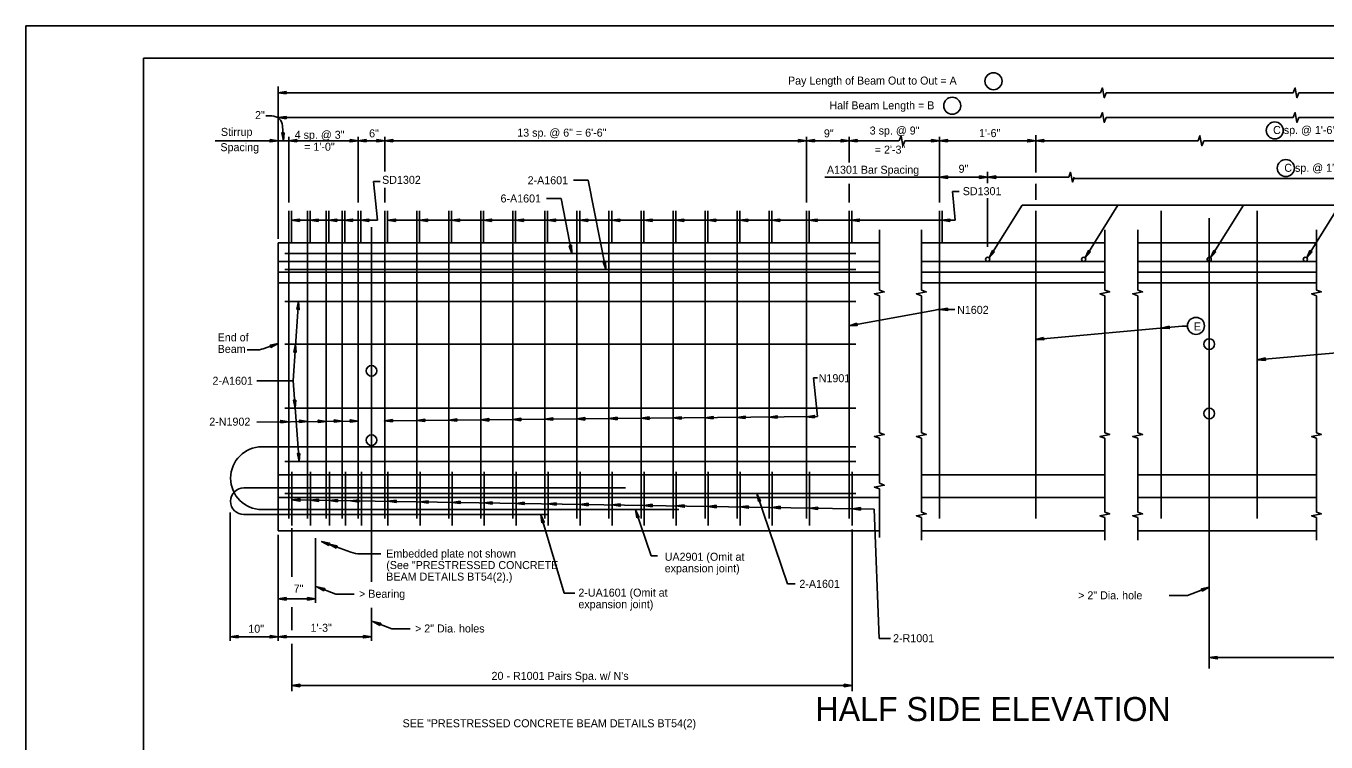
# Model space of a CAD drawing. Extents: x -125.5 to -89.3, y 42.4 to 64.4.
# Drawn here: x -125.53 to -105.23, y 53.27 to 64.45 of the extents above; entities that cross this region are included whole.
import ezdxf

# ---------------------------------------------------------------- set-up
doc = ezdxf.new("R2010")
doc.units = 0
for name, color, linetype in [('BR_AUTO DIMENSION', 7, 'Continuous'), ('BR_BORDER LINES', 7, 'Continuous'), ('BR_CENTER LINES', 7, 'Continuous'), ('BR_PRESTRESSED BEAM', 7, 'Continuous'), ('BR_REBAR', 7, 'Continuous'), ('BR_TEXT', 7, 'Continuous'), ('Level 31', 7, 'Continuous')]:
    doc.layers.add(name, color=color, linetype=linetype)

msp = doc.modelspace()

# ---------------------------------------------------------------- linework, layer by layer
at = {"layer": 'BR_AUTO DIMENSION'}
for p, q in [((-121.596, 61.128), (-121.596, 63.505)), ((-121.596, 63.406), (-108.753, 63.406)), ((-108.666, 63.406), (-105.743, 63.406)), ((-105.657, 63.406), (-98.103, 63.406)), ((-121.693, 63.044), (-121.789, 63.044)), ((-121.596, 63.019), (-108.753, 63.019)), ((-108.666, 63.019), (-105.743, 63.019)), ((-105.657, 63.019), (-98.103, 63.019)), ((-121.512, 62.657), (-121.526, 62.888)), ((-109.766, 62.162), (-109.766, 62.743)), ((-122.577, 62.657), (-114.512, 62.657)), ((-121.429, 61.693), (-121.429, 62.719)), ((-120.346, 61.693), (-120.346, 62.719)), ((-119.929, 62.177), (-119.929, 62.719)), ((-114.512, 62.657), (-113.679, 62.657)), ((-113.679, 62.657), (-111.903, 62.657)), ((-113.346, 61.693), (-113.346, 62.719)), ((-112.679, 62.317), (-112.679, 62.719)), ((-111.81, 62.657), (-107.23, 62.657)), ((-111.266, 61.693), (-111.266, 62.719)), ((-107.143, 62.657), (-98.857, 62.657)), ((-110.516, 61.996), (-110.516, 62.174)), ((-120.108, 62.019), (-120.004, 62.019)), ((-120.045, 61.416), (-120.108, 62.019)), ((-119.929, 61.693), (-119.929, 61.92)), ((-116.754, 62.042), (-116.985, 62.042)), ((-116.478, 60.648), (-116.754, 62.042)), ((-113.061, 62.088), (-109.251, 62.088)), ((-112.679, 61.693), (-112.679, 61.983)), ((-109.766, 61.735), (-109.766, 61.984)), ((-109.164, 62.067), (-98.857, 62.067)), ((-117.177, 61.757), (-117.407, 61.757)), ((-117.007, 60.898), (-117.177, 61.757)), ((-111.064, 61.866), (-110.96, 61.866)), ((-111.025, 61.416), (-111.064, 61.866)), ((-110.516, 60.999), (-110.516, 61.762)), ((-110.491, 60.827), (-109.978, 61.65)), ((-109.978, 61.65), (-103.514, 61.65)), ((-108.995, 60.827), (-108.481, 61.65)), ((-107.035, 60.827), (-106.522, 61.65)), ((-105.534, 60.827), (-105.021, 61.65)), ((-120.045, 61.416), (-121.387, 61.416)), ((-111.025, 61.416), (-119.887, 61.416)), ((-121.288, 59.992), (-121.277, 60.148)), ((-121.362, 58.906), (-121.288, 59.992)), ((-112.679, 59.769), (-111.337, 60.014)), ((-111.248, 60.022), (-111.03, 60.022)), ((-106.306, 59.235), (-98.317, 59.954)), ((-109.766, 59.555), (-107.477, 59.761)), ((-107.477, 59.761), (-107.395, 59.761)), ((-121.831, 59.408), (-121.596, 59.49)), ((-122.078, 59.39), (-121.94, 59.39)), ((-121.927, 58.906), (-121.362, 58.906)), ((-121.362, 58.906), (-121.267, 57.648)), ((-113.175, 58.35), (-113.238, 58.953)), ((-113.238, 58.953), (-113.174, 58.953)), ((-120.346, 58.28), (-121.926, 58.265)), ((-113.175, 58.35), (-119.935, 58.284)), ((-121.38, 57.05), (-112.286, 56.905)), ((-114.12, 57.148), (-113.642, 55.738)), ((-122.346, 56.852), (-122.346, 54.85)), ((-116.016, 56.895), (-115.773, 56.176)), ((-112.286, 56.905), (-112.21, 54.883)), ((-117.495, 56.818), (-117.131, 55.594)), ((-121.596, 56.503), (-121.596, 54.85)), ((-121.38, 56.607), (-121.38, 55.85)), ((-121.012, 56.453), (-121.012, 55.443)), ((-112.63, 56.586), (-112.63, 54.064)), ((-120.459, 56.233), (-120.916, 56.399)), ((-119.991, 56.208), (-120.317, 56.208)), ((-115.773, 56.176), (-115.671, 56.176)), ((-120.992, 55.693), (-120.694, 55.579)), ((-113.642, 55.738), (-113.524, 55.738)), ((-107.056, 55.685), (-107.395, 55.555)), ((-121.012, 55.505), (-121.596, 55.505)), ((-120.694, 55.579), (-120.406, 55.579)), ((-117.131, 55.594), (-116.96, 55.595)), ((-107.395, 55.555), (-107.683, 55.555)), ((-121.38, 55.373), (-121.38, 55.016)), ((-120.117, 55.151), (-119.82, 55.037)), ((-119.82, 55.037), (-119.532, 55.037)), ((-121.596, 54.912), (-122.346, 54.912)), ((-120.138, 54.912), (-121.596, 54.912)), ((-112.21, 54.883), (-112.033, 54.883)), ((-121.38, 54.804), (-121.38, 54.064)), ((-102.877, 54.586), (-107.056, 54.586)), ((-121.38, 54.151), (-112.63, 54.151))]:
    msp.add_line(p, q, dxfattribs=at)
for points in [[(-121.471, 63.387), (-121.596, 63.406), (-121.471, 63.425)], [(-121.471, 63.001), (-121.596, 63.019), (-121.471, 63.038)], [(-121.501, 62.783), (-121.512, 62.657), (-121.539, 62.78)], [(-121.721, 62.676), (-121.596, 62.657), (-121.721, 62.638)], [(-121.304, 62.638), (-121.429, 62.657), (-121.304, 62.676)], [(-120.471, 62.676), (-120.346, 62.657), (-120.471, 62.638)], [(-120.221, 62.638), (-120.346, 62.657), (-120.221, 62.676)], [(-120.054, 62.676), (-119.929, 62.657), (-120.054, 62.638)], [(-119.804, 62.638), (-119.929, 62.657), (-119.804, 62.676)], [(-113.471, 62.676), (-113.346, 62.657), (-113.471, 62.638)], [(-113.221, 62.638), (-113.346, 62.657), (-113.221, 62.676)], [(-112.804, 62.676), (-112.679, 62.657), (-112.804, 62.638)], [(-112.554, 62.638), (-112.679, 62.657), (-112.554, 62.676)], [(-111.391, 62.676), (-111.266, 62.657), (-111.391, 62.638)], [(-111.141, 62.638), (-111.266, 62.657), (-111.141, 62.676)], [(-109.891, 62.676), (-109.766, 62.657), (-109.891, 62.638)], [(-109.641, 62.676), (-109.766, 62.657), (-109.641, 62.638)], [(-111.141, 62.107), (-111.266, 62.088), (-111.141, 62.069)], [(-110.641, 62.107), (-110.516, 62.088), (-110.641, 62.069)], [(-110.391, 62.107), (-110.516, 62.088), (-110.391, 62.069)], [(-121.262, 61.397), (-121.387, 61.416), (-121.262, 61.434)], [(-120.971, 61.397), (-121.096, 61.416), (-120.971, 61.434)], [(-120.679, 61.397), (-120.804, 61.416), (-120.679, 61.434)], [(-120.432, 61.397), (-120.557, 61.416), (-120.432, 61.434)], [(-120.18, 61.397), (-120.305, 61.416), (-120.18, 61.434)], [(-119.762, 61.397), (-119.887, 61.416), (-119.762, 61.434)], [(-119.262, 61.397), (-119.387, 61.416), (-119.262, 61.434)], [(-118.762, 61.397), (-118.887, 61.416), (-118.762, 61.434)], [(-118.262, 61.397), (-118.387, 61.416), (-118.262, 61.434)], [(-117.762, 61.397), (-117.887, 61.416), (-117.762, 61.434)], [(-117.262, 61.397), (-117.387, 61.416), (-117.262, 61.434)], [(-116.762, 61.397), (-116.887, 61.416), (-116.762, 61.434)], [(-116.262, 61.397), (-116.387, 61.416), (-116.262, 61.434)], [(-115.756, 61.397), (-115.881, 61.416), (-115.756, 61.434)], [(-115.262, 61.397), (-115.387, 61.416), (-115.262, 61.434)], [(-114.762, 61.397), (-114.887, 61.416), (-114.762, 61.434)], [(-114.262, 61.397), (-114.387, 61.416), (-114.262, 61.434)], [(-113.762, 61.397), (-113.887, 61.416), (-113.762, 61.434)], [(-113.179, 61.397), (-113.304, 61.416), (-113.179, 61.434)], [(-112.521, 61.397), (-112.646, 61.416), (-112.521, 61.434)], [(-111.108, 61.397), (-111.233, 61.416), (-111.108, 61.434)], [(-117.049, 61.017), (-117.007, 60.898), (-117.012, 61.025)], [(-110.408, 60.923), (-110.491, 60.827), (-110.44, 60.943)], [(-108.912, 60.923), (-108.995, 60.827), (-108.943, 60.943)], [(-106.952, 60.923), (-107.035, 60.827), (-106.984, 60.943)], [(-105.451, 60.923), (-105.534, 60.827), (-105.483, 60.943)], [(-116.521, 60.767), (-116.478, 60.648), (-116.484, 60.775)], [(-121.304, 60.025), (-121.277, 60.148), (-121.267, 60.022)], [(-111.141, 60.045), (-111.265, 60.022), (-111.14, 60.008)], [(-112.559, 59.81), (-112.679, 59.769), (-112.553, 59.773)], [(-107.683, 59.761), (-107.806, 59.731), (-107.68, 59.724)], [(-121.708, 59.431), (-121.596, 59.49), (-121.72, 59.467)], [(-121.35, 59.358), (-121.322, 59.482), (-121.312, 59.356)], [(-109.643, 59.584), (-109.766, 59.555), (-109.64, 59.547)], [(-106.183, 59.265), (-106.306, 59.235), (-106.18, 59.227)], [(-121.321, 58.608), (-121.33, 58.482), (-121.358, 58.605)], [(-121.554, 58.253), (-121.429, 58.27), (-121.554, 58.29)], [(-121.263, 58.256), (-121.137, 58.272), (-121.262, 58.293)], [(-120.971, 58.258), (-120.846, 58.275), (-120.97, 58.296)], [(-120.721, 58.261), (-120.596, 58.278), (-120.72, 58.298)], [(-120.471, 58.263), (-120.346, 58.28), (-120.47, 58.301)], [(-119.809, 58.266), (-119.935, 58.283), (-119.81, 58.304)], [(-119.304, 58.271), (-119.429, 58.288), (-119.304, 58.309)], [(-118.804, 58.276), (-118.929, 58.293), (-118.804, 58.314)], [(-118.304, 58.281), (-118.429, 58.298), (-118.304, 58.319)], [(-117.804, 58.286), (-117.929, 58.303), (-117.804, 58.323)], [(-117.304, 58.292), (-117.429, 58.309), (-117.304, 58.329)], [(-116.804, 58.296), (-116.929, 58.313), (-116.804, 58.334)], [(-116.304, 58.301), (-116.429, 58.318), (-116.304, 58.339)], [(-115.804, 58.306), (-115.929, 58.323), (-115.804, 58.344)], [(-115.304, 58.311), (-115.429, 58.328), (-115.304, 58.348)], [(-114.804, 58.316), (-114.929, 58.333), (-114.804, 58.353)], [(-114.304, 58.321), (-114.429, 58.338), (-114.304, 58.358)], [(-113.804, 58.326), (-113.929, 58.342), (-113.804, 58.363)], [(-113.22, 58.331), (-113.346, 58.348), (-113.221, 58.369)], [(-121.258, 57.775), (-121.267, 57.648), (-121.295, 57.772)], [(-121.254, 57.067), (-121.38, 57.05), (-121.255, 57.029)], [(-120.963, 57.062), (-121.088, 57.045), (-120.963, 57.025)], [(-120.671, 57.057), (-120.796, 57.04), (-120.671, 57.02)], [(-120.338, 57.052), (-120.463, 57.035), (-120.338, 57.015)], [(-119.754, 57.044), (-119.88, 57.027), (-119.755, 57.007)], [(-114.097, 57.024), (-114.12, 57.148), (-114.062, 57.036)], [(-119.254, 57.036), (-119.38, 57.019), (-119.255, 56.999)], [(-118.754, 57.028), (-118.88, 57.011), (-118.755, 56.991)], [(-118.254, 57.02), (-118.38, 57.003), (-118.255, 56.983)], [(-117.754, 57.012), (-117.88, 56.995), (-117.755, 56.975)], [(-117.254, 57.004), (-117.38, 56.987), (-117.255, 56.967)], [(-116.754, 56.996), (-116.88, 56.979), (-116.755, 56.959)], [(-116.254, 56.989), (-116.38, 56.972), (-116.255, 56.951)], [(-115.994, 56.77), (-116.016, 56.895), (-115.958, 56.782)], [(-115.754, 56.981), (-115.88, 56.964), (-115.755, 56.943)], [(-115.254, 56.973), (-115.38, 56.956), (-115.255, 56.935)], [(-114.754, 56.965), (-114.88, 56.948), (-114.755, 56.927)], [(-114.254, 56.957), (-114.38, 56.94), (-114.255, 56.919)], [(-113.754, 56.949), (-113.879, 56.932), (-113.755, 56.911)], [(-113.17, 56.938), (-113.295, 56.921), (-113.171, 56.901)], [(-112.503, 56.928), (-112.629, 56.911), (-112.504, 56.89)], [(-117.477, 56.693), (-117.495, 56.818), (-117.441, 56.704)], [(-120.805, 56.338), (-120.916, 56.399), (-120.792, 56.374)], [(-120.688, 56.296), (-120.799, 56.356), (-120.675, 56.331)], [(-120.882, 55.631), (-120.992, 55.693), (-120.868, 55.666)], [(-107.166, 55.623), (-107.056, 55.685), (-107.179, 55.658)], [(-121.471, 55.486), (-121.596, 55.505), (-121.471, 55.524)], [(-121.137, 55.524), (-121.012, 55.505), (-121.137, 55.486)], [(-120.007, 55.089), (-120.117, 55.151), (-119.993, 55.124)], [(-122.221, 54.893), (-122.346, 54.912), (-122.221, 54.931)], [(-121.721, 54.931), (-121.596, 54.912), (-121.721, 54.893)], [(-121.471, 54.893), (-121.596, 54.912), (-121.471, 54.931)], [(-120.263, 54.931), (-120.138, 54.912), (-120.263, 54.893)], [(-106.931, 54.605), (-107.056, 54.586), (-106.931, 54.567)], [(-121.255, 54.132), (-121.38, 54.151), (-121.255, 54.17)], [(-112.755, 54.17), (-112.63, 54.151), (-112.755, 54.132)]]:
    msp.add_lwpolyline(points, close=True, dxfattribs=at)
for points in [[(-108.753, 63.406), (-108.724, 63.483), (-108.695, 63.329), (-108.666, 63.406)], [(-105.743, 63.406), (-105.714, 63.483), (-105.686, 63.329), (-105.657, 63.406)], [(-108.753, 63.019), (-108.724, 63.096), (-108.695, 62.942), (-108.666, 63.019)], [(-105.743, 63.019), (-105.714, 63.096), (-105.686, 62.942), (-105.657, 63.019)], [(-111.896, 62.657), (-111.867, 62.734), (-111.839, 62.58), (-111.81, 62.657)], [(-107.23, 62.657), (-107.201, 62.734), (-107.172, 62.58), (-107.143, 62.657)], [(-109.251, 62.088), (-109.222, 62.165), (-109.193, 62.011), (-109.164, 62.088)]]:
    msp.add_lwpolyline(points, dxfattribs=at)
for centre, radius, start, end in [((-121.693, 62.878), 0.167, 3.4775, 90), ((-111.248, 59.522), 0.5, 90, 100.3446), ((-121.94, 59.723), 0.333, 270, 289.1163), ((-120.317, 56.625), 0.417, 250.1289, 270)]:
    msp.add_arc(centre, radius, start, end, dxfattribs=at)
at = {"layer": 'BR_BORDER LINES'}
for p in [(-90.033, 63.949), (-123.699, 42.949)]:
    msp.add_line(p, (-123.699, 63.949), dxfattribs=at)
at = {"layer": 'BR_CENTER LINES'}
for p, q in [((-120.138, 61.309), (-120.138, 55.771)), ((-107.056, 61.449), (-107.056, 54.416)), ((-112.207, 61.265), (-112.207, 60.325)), ((-111.551, 61.265), (-111.551, 60.325)), ((-108.686, 61.265), (-108.686, 60.325)), ((-108.173, 61.265), (-108.173, 60.325)), ((-105.381, 61.265), (-105.381, 60.325)), ((-112.207, 60.238), (-112.207, 58.098)), ((-111.551, 60.238), (-111.551, 58.098)), ((-108.686, 60.238), (-108.686, 58.098)), ((-108.173, 60.238), (-108.173, 58.098)), ((-105.381, 60.238), (-105.381, 58.098)), ((-112.207, 58.011), (-112.207, 57.308)), ((-111.551, 58.011), (-111.551, 56.859)), ((-108.686, 58.011), (-108.686, 56.859)), ((-108.173, 58.011), (-108.173, 56.859)), ((-105.381, 58.011), (-105.381, 56.859)), ((-112.207, 57.221), (-112.207, 56.46)), ((-111.551, 56.772), (-111.551, 56.423)), ((-108.686, 56.772), (-108.686, 56.423)), ((-108.173, 56.772), (-108.173, 56.423)), ((-105.381, 56.772), (-105.381, 56.423)), ((-120.138, 55.362), (-120.138, 54.85))]:
    msp.add_line(p, q, dxfattribs=at)
for points in [[(-112.207, 60.325), (-112.13, 60.296), (-112.284, 60.267), (-112.207, 60.238)], [(-111.551, 60.325), (-111.474, 60.296), (-111.628, 60.267), (-111.551, 60.238)], [(-108.686, 60.325), (-108.609, 60.296), (-108.763, 60.267), (-108.686, 60.238)], [(-108.173, 60.325), (-108.096, 60.296), (-108.251, 60.267), (-108.173, 60.238)], [(-105.381, 60.325), (-105.304, 60.296), (-105.458, 60.267), (-105.381, 60.238)], [(-112.207, 58.098), (-112.13, 58.069), (-112.284, 58.04), (-112.207, 58.011)], [(-111.551, 58.098), (-111.474, 58.069), (-111.628, 58.04), (-111.551, 58.011)], [(-108.686, 58.098), (-108.609, 58.069), (-108.763, 58.04), (-108.686, 58.011)], [(-108.173, 58.098), (-108.096, 58.069), (-108.251, 58.04), (-108.173, 58.011)], [(-105.381, 58.098), (-105.304, 58.069), (-105.458, 58.04), (-105.381, 58.011)], [(-112.207, 57.308), (-112.13, 57.279), (-112.284, 57.25), (-112.207, 57.221)], [(-111.551, 56.859), (-111.474, 56.83), (-111.628, 56.801), (-111.551, 56.772)], [(-108.686, 56.859), (-108.609, 56.83), (-108.763, 56.801), (-108.686, 56.772)], [(-108.173, 56.859), (-108.096, 56.83), (-108.251, 56.801), (-108.173, 56.772)], [(-105.381, 56.859), (-105.304, 56.83), (-105.458, 56.801), (-105.381, 56.772)]]:
    msp.add_lwpolyline(points, dxfattribs=at)
at = {"layer": 'BR_PRESTRESSED BEAM'}
for p, q in [((-121.596, 61.065), (-112.207, 61.065)), ((-121.596, 61.065), (-121.596, 56.565)), ((-111.551, 61.065), (-108.686, 61.065)), ((-108.173, 61.065), (-105.381, 61.065)), ((-121.596, 60.773), (-112.207, 60.773)), ((-111.551, 60.773), (-108.686, 60.773)), ((-108.173, 60.773), (-105.381, 60.773)), ((-121.596, 60.607), (-112.207, 60.607)), ((-111.551, 60.607), (-108.686, 60.607)), ((-108.173, 60.607), (-105.381, 60.607)), ((-121.596, 60.44), (-112.207, 60.44)), ((-111.551, 60.44), (-108.686, 60.44)), ((-108.173, 60.44), (-105.381, 60.44)), ((-121.596, 57.44), (-112.207, 57.44)), ((-111.551, 57.44), (-108.686, 57.44)), ((-108.173, 57.44), (-105.381, 57.44)), ((-121.596, 57.086), (-112.207, 57.086)), ((-111.551, 57.086), (-108.686, 57.086)), ((-108.173, 57.086), (-105.381, 57.086)), ((-121.596, 56.565), (-112.207, 56.565)), ((-111.551, 56.565), (-108.686, 56.565)), ((-108.173, 56.565), (-105.381, 56.565))]:
    msp.add_line(p, q, dxfattribs=at)
for centre, radius in [((-107.056, 59.482), 0.0833), ((-120.138, 59.065), 0.0834), ((-107.056, 58.398), 0.0833), ((-120.138, 57.982), 0.0834)]:
    msp.add_circle(centre, radius, dxfattribs=at)
at = {"layer": 'BR_REBAR'}
for p, q in [((-121.429, 61.565), (-121.429, 56.757)), ((-121.387, 61.565), (-121.387, 61.055)), ((-121.137, 61.565), (-121.137, 56.757)), ((-121.096, 61.565), (-121.096, 61.055)), ((-120.846, 61.565), (-120.846, 56.757)), ((-120.804, 61.565), (-120.804, 61.055)), ((-120.596, 61.565), (-120.596, 56.757)), ((-120.554, 61.565), (-120.554, 61.055)), ((-120.346, 61.565), (-120.346, 56.757)), ((-120.304, 61.565), (-120.304, 61.055)), ((-119.929, 61.565), (-119.929, 56.757)), ((-119.887, 61.565), (-119.887, 61.055)), ((-119.429, 61.565), (-119.429, 56.757)), ((-119.387, 61.565), (-119.387, 61.055)), ((-118.929, 61.565), (-118.929, 56.757)), ((-118.887, 61.565), (-118.887, 61.055)), ((-118.429, 61.565), (-118.429, 56.757)), ((-118.387, 61.565), (-118.387, 61.055)), ((-117.929, 61.565), (-117.929, 56.757)), ((-117.887, 61.565), (-117.887, 61.055)), ((-117.429, 61.565), (-117.429, 56.757)), ((-117.387, 61.565), (-117.387, 61.055)), ((-116.929, 61.565), (-116.929, 56.757)), ((-116.887, 61.565), (-116.887, 61.055)), ((-116.429, 61.565), (-116.429, 59.104)), ((-116.387, 61.565), (-116.387, 61.055)), ((-115.929, 61.565), (-115.929, 56.757)), ((-115.887, 61.565), (-115.887, 61.055)), ((-115.429, 61.565), (-115.429, 56.757)), ((-115.387, 61.565), (-115.387, 61.055)), ((-114.929, 61.565), (-114.929, 56.757)), ((-114.887, 61.565), (-114.887, 61.055)), ((-114.429, 61.565), (-114.429, 56.757)), ((-114.387, 61.565), (-114.387, 61.055)), ((-113.929, 61.565), (-113.929, 56.757)), ((-113.887, 61.565), (-113.887, 61.055)), ((-113.346, 61.565), (-113.346, 56.757)), ((-113.304, 61.565), (-113.304, 61.055)), ((-112.679, 61.565), (-112.679, 56.757)), ((-112.637, 61.565), (-112.637, 61.055)), ((-111.266, 61.565), (-111.266, 56.757)), ((-111.224, 61.565), (-111.224, 61.055)), ((-109.766, 61.565), (-109.766, 59.702)), ((-107.806, 61.565), (-107.806, 56.757)), ((-106.306, 61.565), (-106.306, 56.757)), ((-121.49, 60.898), (-112.572, 60.898)), ((-121.49, 60.648), (-112.572, 60.648)), ((-121.49, 60.148), (-112.572, 60.148)), ((-109.766, 59.702), (-109.766, 56.757)), ((-121.49, 59.482), (-112.572, 59.482)), ((-116.429, 59.104), (-116.429, 56.757)), ((-121.49, 58.482), (-112.572, 58.482)), ((-121.848, 57.878), (-112.572, 57.878)), ((-121.49, 57.648), (-112.572, 57.648)), ((-121.38, 56.648), (-121.38, 57.487)), ((-121.088, 56.648), (-121.088, 57.487)), ((-120.796, 56.648), (-120.796, 57.487)), ((-120.546, 56.648), (-120.546, 57.487)), ((-120.296, 56.648), (-120.296, 57.487)), ((-119.88, 56.648), (-119.88, 57.487)), ((-119.38, 56.648), (-119.38, 57.487)), ((-118.88, 56.648), (-118.88, 57.487)), ((-118.38, 56.648), (-118.38, 57.487)), ((-117.88, 56.648), (-117.88, 57.487)), ((-117.38, 56.648), (-117.38, 57.487)), ((-116.88, 56.648), (-116.88, 57.487)), ((-116.38, 56.648), (-116.38, 57.487)), ((-115.88, 56.648), (-115.88, 57.487)), ((-115.38, 56.648), (-115.38, 57.487)), ((-114.88, 56.648), (-114.88, 57.487)), ((-114.38, 56.648), (-114.38, 57.487)), ((-113.88, 56.648), (-113.88, 57.487)), ((-113.296, 56.648), (-113.296, 57.487)), ((-112.63, 56.648), (-112.63, 57.487)), ((-122.13, 57.236), (-116.171, 57.236)), ((-121.49, 57.148), (-112.572, 57.148)), ((-121.848, 56.898), (-115.338, 56.898)), ((-122.13, 56.819), (-117.374, 56.819))]:
    msp.add_line(p, q, dxfattribs=at)
for centre in [(-110.516, 60.806), (-109.016, 60.806), (-107.056, 60.806), (-105.556, 60.806)]:
    msp.add_circle(centre, 0.0326, dxfattribs=at)
for centre, radius in [((-121.848, 57.388), 0.49), ((-122.13, 57.028), 0.208)]:
    msp.add_arc(centre, radius, 90, 270, dxfattribs=at)
at = {"layer": 'BR_TEXT'}
for centre in [(-110.425, 63.587), (-111.07, 63.204), (-106.033, 62.818), (-105.86, 62.231), (-107.263, 59.766)]:
    msp.add_circle(centre, 0.133, dxfattribs=at)
at = {"layer": 'Level 31'}
msp.add_lwpolyline([(-125.533, 42.449), (-89.533, 42.449), (-89.533, 64.449), (-125.533, 64.449)], close=True, dxfattribs=at)

# ---------------------------------------------------------------- texts
at = {"layer": 'BR_AUTO DIMENSION'}
for s, height, p in [('Pay Length of Beam Out to Out = A', 0.125, (-113.634, 63.534)), ('Half Beam Length = B', 0.125, (-112.988, 63.147)), ('2"', 0.125, (-121.956, 62.995)), ('Stirrup', 0.125, (-122.489, 62.733)), ('4 sp. @ 3" ', 0.125, (-121.337, 62.688)), ('6"', 0.125, (-120.175, 62.71)), ('13 sp. @ 6" = 6\'-6"', 0.125, (-117.862, 62.721)), ('9"', 0.125, (-113.073, 62.71)), ('3 sp. @ 9"', 0.125, (-112.358, 62.754)), ('1\'-6"', 0.125, (-110.651, 62.714)), ('C sp. @ 1\'-6" =  D', 0.125, (-106.059, 62.762)), ('Spacing', 0.125, (-122.497, 62.494)), ('= 1\'-0"', 0.125, (-121.189, 62.501)), ('= 2\'-3"', 0.125, (-112.279, 62.456)), ('A1301 Bar Spacing', 0.125, (-113.026, 62.142)), ('9"', 0.125, (-110.97, 62.157)), ('C sp. @ 1\'-6" =  D', 0.125, (-105.884, 62.172)), ('SD1302', 0.125, (-119.972, 61.984)), ('SD1301', 0.125, (-110.905, 61.807)), ('E', 0.125, (-107.295, 59.695)), ('End of', 0.125, (-122.54, 59.525)), ('Beam', 0.125, (-122.54, 59.344)), ('Embedded plate not shown', 0.125, (-119.907, 56.149)), ('(See "PRESTRESSED CONCRETE', 0.125, (-119.907, 55.969)), ('BEAM DETAILS BT54(2).)', 0.125, (-119.907, 55.789)), ('7"', 0.125, (-121.353, 55.603)), ('> Bearing', 0.125, (-120.332, 55.521)), ('> 2" Dia. hole', 0.125, (-109.103, 55.497)), ('10"', 0.125, (-122.061, 54.975)), ('1\'-3"', 0.125, (-121.09, 54.99)), ('> 2" Dia. holes', 0.125, (-119.458, 54.979)), ("20 - R1001 Pairs Spa. w/ N's", 0.125, (-118.263, 54.239)), ('HALF SIDE ELEVATION', 0.375, (-113.204, 53.596))]:
    msp.add_text(s, height=height, dxfattribs=at).set_placement(p)
for s, p in [('2-A1601', (-117.7, 61.977)), ('6-A1601', (-118.123, 61.693))]:
    msp.add_text(s, height=0.125, rotation=360, dxfattribs=at).set_placement(p)
at = {"layer": 'BR_TEXT'}
for s, p in [('N1602', (-110.993, 59.954)), ('2-A1601', (-122.621, 58.847)), ('N1901', (-113.154, 58.887)), ('2-N1902', (-122.671, 58.208)), ('expansion joint)', (-115.559, 55.919)), ('UA2901 (Omit at ', (-115.559, 56.099)), ('2-UA1601 (Omit at ', (-116.907, 55.539)), ('2-A1601', (-113.456, 55.676)), ('expansion joint)', (-116.907, 55.358)), ('2-R1001', (-111.993, 54.827)), ('SEE "PRESTRESSED CONCRETE BEAM DETAILS BT54(2)', (-119.652, 53.499))]:
    msp.add_text(s, height=0.125, dxfattribs=at).set_placement(p)

doc.saveas('drawing.dxf')
